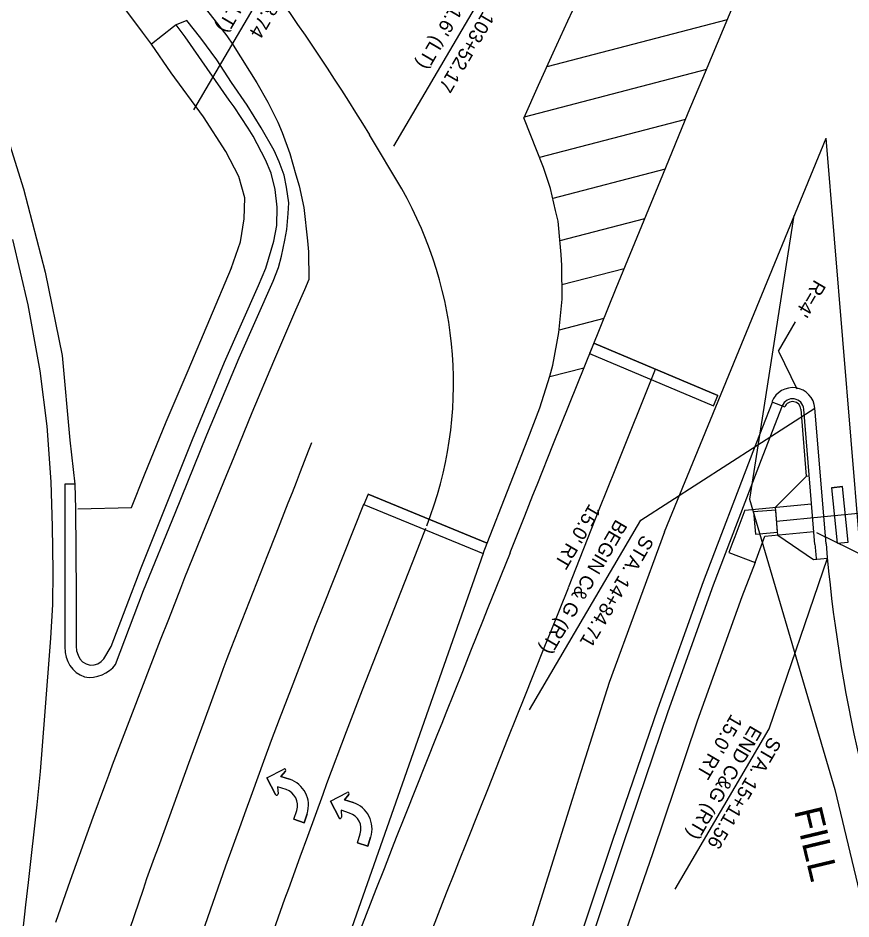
# Model space of a CAD drawing. Extents: x 1730210 to 1732101, y 650763 to 653427.
# Drawn here: x 1730371.6 to 1730520.8, y 652788.8 to 652950.2 of the extents above; entities that cross this region are included whole.
import ezdxf

# ---------------------------------------------------------------- set-up
doc = ezdxf.new("R2010")
doc.units = 0
for name, color, linetype in [('DESIGN - ROW - Slope Lines', 7, 'Continuous'), ('DESIGN - ROW - Slope Lines Text', 7, 'Continuous'), ('DESIGN - TRAFFIC CONTROL PERMANENT - Pavement Marking', 7, 'Continuous'), ('DESIGN - TRANSPORTATION - Curb Gutter and Sidewalk', 7, 'Continuous'), ('DESIGN - TRANSPORTATION - Edge of Traveled Way', 7, 'Continuous'), ('DESIGN - TRANSPORTATION - Shoulder Lines', 7, 'Continuous'), ('DESIGN - TRANSPORTATION - Text', 7, 'Continuous'), ('FUNCTIONAL - TRANSPORTATION - Preliminary Edge of Traveled Way', 7, 'Continuous'), ('SURVEY - TRANSPORTATION - Features', 7, 'Continuous')]:
    doc.layers.add(name, color=color, linetype=linetype)

msp = doc.modelspace()

# ---------------------------------------------------------------- linework, layer by layer
at = {"layer": 'DESIGN - ROW - Slope Lines'}
for p, q in [((1730510.54, 652914.84), (1730502.62, 652864.02)), ((1730502.62, 652864.02), (1730517.89, 652812.05)), ((1730517.89, 652812.05), (1730530.41, 652759.65))]:
    msp.add_line(p, q, dxfattribs=at)
at = {"layer": 'DESIGN - TRAFFIC CONTROL PERMANENT - Pavement Marking'}
for p, q in [((1730498.6, 652949.88), (1730466.28, 652941.47)), ((1730494.88, 652940.95), (1730462.22, 652932.45)), ((1730491.16, 652932.03), (1730465, 652925.22)), ((1730440.3, 652919.58), (1730434.56, 652929.27)), ((1730487.47, 652923.11), (1730467.37, 652917.88)), ((1730483.8, 652914.2), (1730468.65, 652910.26)), ((1730480.13, 652905.29), (1730469.01, 652902.39)), ((1730476.51, 652896.39), (1730468.51, 652894.3)), ((1730474.72, 652891.95), (1730496.91, 652882.58)), ((1730472.93, 652887.5), (1730466.81, 652885.91)), ((1730517.29, 652866.08), (1730519.28, 652866.29)), ((1730434.3, 652864.9), (1730455.63, 652856.17)), ((1730518.3, 652856.13), (1730520.29, 652856.34)), ((1730454.87, 652854.32), (1730406.19, 652715.68)), ((1730416.15, 652814.15), (1730419.16, 652815.69)), ((1730416.15, 652814.15), (1730419.16, 652815.69)), ((1730419.46, 652815.31), (1730418.66, 652814.38)), ((1730418.66, 652814.38), (1730419.46, 652815.31)), ((1730418.66, 652814.38), (1730420.2, 652813.88)), ((1730420.2, 652813.88), (1730418.66, 652814.38)), ((1730417.69, 652811.15), (1730416.15, 652814.15)), ((1730416.15, 652814.15), (1730417.69, 652811.15)), ((1730419.59, 652812.01), (1730418.05, 652812.5)), ((1730418.05, 652812.5), (1730418.15, 652811.28)), ((1730419.59, 652812.01), (1730418.05, 652812.5)), ((1730418.05, 652812.5), (1730418.15, 652811.28)), ((1730427.53, 652809.97), (1730430.54, 652811.5)), ((1730427.53, 652809.97), (1730430.54, 652811.5)), ((1730430.83, 652811.13), (1730430.04, 652810.19)), ((1730430.04, 652810.19), (1730430.83, 652811.13)), ((1730429.07, 652806.96), (1730427.53, 652809.97)), ((1730427.53, 652809.97), (1730429.07, 652806.96)), ((1730430.04, 652810.19), (1730431.58, 652809.69)), ((1730431.58, 652809.69), (1730430.04, 652810.19)), ((1730420.98, 652806.69), (1730421.49, 652808.29)), ((1730420.98, 652806.69), (1730421.49, 652808.29)), ((1730430.97, 652807.82), (1730429.43, 652808.32)), ((1730429.43, 652808.32), (1730429.53, 652807.09)), ((1730430.97, 652807.82), (1730429.43, 652808.32)), ((1730429.43, 652808.32), (1730429.53, 652807.09)), ((1730422.85, 652806.09), (1730420.98, 652806.69)), ((1730420.98, 652806.69), (1730422.85, 652806.09)), ((1730423.36, 652807.68), (1730422.85, 652806.09)), ((1730422.85, 652806.09), (1730423.36, 652807.68)), ((1730432.36, 652802.51), (1730432.87, 652804.1)), ((1730432.36, 652802.51), (1730432.87, 652804.1)), ((1730434.74, 652803.5), (1730434.23, 652801.9)), ((1730434.23, 652801.9), (1730434.74, 652803.5)), ((1730434.23, 652801.9), (1730432.36, 652802.51)), ((1730432.36, 652802.51), (1730434.23, 652801.9))]:
    msp.add_line(p, q, dxfattribs=at)
for points in [[(1730459.75, 652854.49), (1730462.34, 652861.01), (1730463.81, 652864.72), (1730464.55, 652866.58), (1730467.49, 652874.01), (1730478.69, 652901.8), (1730487.06, 652922.11), (1730491.64, 652933.19), (1730494.71, 652940.56), (1730500.09, 652953.46), (1730503.24, 652960.81), (1730505.59, 652966.32), (1730506.38, 652968.16), (1730507.95, 652971.83), (1730508.73, 652973.66), (1730510.3, 652977.33), (1730518.04, 652995.02)], [(1730385.19, 652976.62), (1730390.46, 652970.6), (1730397.86, 652961.16), (1730404.04, 652953.3), (1730407.74, 652948.58), (1730408.98, 652947.01), (1730410.08, 652945.35), (1730414.32, 652938.57), (1730416.33, 652935.1), (1730417.24, 652933.33), (1730418.1, 652931.52), (1730418.91, 652929.69), (1730420.24, 652925.92), (1730421.36, 652922.08), (1730421.91, 652920.16), (1730422.75, 652916.25), (1730423.43, 652910.3), (1730423.58, 652908.3), (1730423.67, 652903.38)], [(1730455.63, 652856.17), (1730462.91, 652874.77), (1730465.04, 652880.37), (1730466.86, 652886.08), (1730467.37, 652888.01), (1730468.1, 652891.93), (1730468.47, 652893.9), (1730469.03, 652899.86), (1730468.99, 652905.85), (1730468.89, 652907.84), (1730468.7, 652909.83), (1730468.3, 652913.8), (1730467.86, 652915.74), (1730466.97, 652919.64), (1730465.72, 652923.43), (1730462.16, 652932.31)], [(1730371.87, 652781.47), (1730372.99, 652791.4), (1730373.44, 652795.37), (1730375.01, 652809.27), (1730375.6, 652815.23), (1730376.39, 652825.2), (1730377.43, 652839.15), (1730377.82, 652845.14), (1730377.84, 652851.14), (1730377.77, 652859.14), (1730377.51, 652867.13), (1730376.77, 652877.11), (1730375.51, 652887.03), (1730373.37, 652898.83), (1730370.67, 652910.52)], [(1730423.67, 652903.38), (1730422.88, 652901.54), (1730421.29, 652897.88), (1730417.34, 652888.7), (1730413.44, 652879.51), (1730409.68, 652870.26), (1730408.92, 652868.41), (1730406.66, 652862.86), (1730405.16, 652859.17), (1730401.42, 652849.91), (1730400.69, 652848.05), (1730399.24, 652844.33), (1730398.51, 652842.47), (1730397.05, 652838.75), (1730392.01, 652825.72), (1730388.46, 652816.39), (1730387.75, 652814.52), (1730387.04, 652812.65), (1730384.99, 652807.03), (1730380.93, 652795.75), (1730379.6, 652791.98), (1730378.28, 652788.22)], [(1730470.16, 652848.2), (1730475.7, 652862.15), (1730478.64, 652869.55), (1730485.78, 652887.28)], [(1730390.82, 652784.73), (1730394.02, 652794.19), (1730394.66, 652796.08), (1730396.03, 652799.83), (1730396.71, 652801.71), (1730398.76, 652807.34), (1730402.18, 652816.72), (1730404.91, 652824.23), (1730406.28, 652827.98), (1730407.65, 652831.74), (1730408.33, 652833.61), (1730409.04, 652835.48), (1730409.77, 652837.34), (1730416.34, 652854.07), (1730417.8, 652857.79), (1730418.53, 652859.65), (1730419.26, 652861.51), (1730419.99, 652863.37), (1730420.71, 652865.23), (1730421.44, 652867.09), (1730422.17, 652868.95), (1730423.63, 652872.67), (1730424.23, 652874.19)], [(1730383.39, 652722.85), (1730386.34, 652732.15), (1730388.22, 652737.84), (1730395.16, 652758.69), (1730396.44, 652762.47), (1730397.08, 652764.36), (1730397.72, 652766.26), (1730400.29, 652773.82), (1730404.2, 652785.15), (1730408.8, 652798.35), (1730410.17, 652802.1), (1730411.54, 652805.86), (1730412.22, 652807.74), (1730413.58, 652811.49), (1730415.63, 652817.12), (1730417, 652820.88), (1730418.42, 652824.61), (1730420.57, 652830.2), (1730422.71, 652835.8), (1730423.43, 652837.66), (1730424.86, 652841.39), (1730426.33, 652845.1), (1730433.49, 652863.11)], [(1730394.34, 652719.4), (1730396.63, 652726.34), (1730398.51, 652732.03), (1730399.14, 652733.92), (1730400.42, 652737.7), (1730405.54, 652752.84), (1730412.73, 652773.6), (1730419.37, 652792.44), (1730420.06, 652794.32), (1730422.11, 652799.95), (1730423.48, 652803.7), (1730424.84, 652807.45), (1730426.21, 652811.21), (1730426.9, 652813.08), (1730430.4, 652822.43), (1730433.3, 652829.88), (1730442.75, 652854.07), (1730444.61, 652858.82)], [(1730406.19, 652715.68), (1730406.87, 652717.55), (1730408.25, 652721.3), (1730412.37, 652732.56), (1730414.44, 652738.18), (1730426.36, 652769.97), (1730435.72, 652794.2), (1730437.19, 652797.91), (1730438.66, 652801.63), (1730439.39, 652803.49), (1730440.86, 652807.2), (1730443.07, 652812.77), (1730444.55, 652816.48), (1730446.78, 652822.05), (1730447.52, 652823.9), (1730448.26, 652825.76), (1730451.23, 652833.18), (1730452.71, 652836.89), (1730454.94, 652842.45), (1730455.69, 652844.3), (1730459.76, 652854.48)], [(1730417.45, 652711.55), (1730418.14, 652713.43), (1730419.51, 652717.18), (1730423.63, 652728.42), (1730425.69, 652734), (1730437.58, 652765.71), (1730446.9, 652789.83), (1730448.35, 652793.51), (1730449.82, 652797.22), (1730450.55, 652799.08), (1730452.01, 652802.79), (1730454.22, 652808.33), (1730455.7, 652812.03), (1730459.4, 652821.3), (1730462.37, 652828.71), (1730463.85, 652832.42), (1730466.08, 652837.98), (1730466.83, 652839.84), (1730470.16, 652848.16)]]:
    msp.add_lwpolyline(points, dxfattribs=at)
for points in [[(1730474.72, 652891.95), (1730473.94, 652890.11), (1730496.14, 652880.74), (1730496.91, 652882.58)], [(1730517.29, 652866.08), (1730518.3, 652856.13), (1730520.29, 652856.34), (1730519.28, 652866.29)], [(1730434.3, 652864.9), (1730433.54, 652863.05), (1730454.87, 652854.32), (1730455.63, 652856.17)]]:
    msp.add_lwpolyline(points, close=True, dxfattribs=at)
for centre, radius, start, end in [((1732146.89, 652178.93), 1845.51, 143.31109, 155.90666), ((1730082.94, 652714.55), 412, 31.4096, 52.3723), ((1730379.58, 652884.74), 70, 338.653, 29.8433), ((1730419.27, 652815.47), 0.246, 319.6308, 117.079), ((1730419.27, 652815.47), 0.246, 319.6308, 117.079), ((1730418.68, 652809.2), 4.92, 342.079, 72.079), ((1730418.68, 652809.2), 4.92, 342.079, 72.079), ((1730417.91, 652811.26), 0.246, 207.079, 4.5722), ((1730417.91, 652811.26), 0.246, 207.079, 4.5722), ((1730418.68, 652809.2), 2.95, 342.079, 72.079), ((1730418.68, 652809.2), 2.95, 342.079, 72.079), ((1730430.65, 652811.29), 0.246, 319.6308, 117.079), ((1730430.65, 652811.29), 0.246, 319.6308, 117.079), ((1730430.06, 652805.01), 4.92, 342.079, 72.079), ((1730430.06, 652805.01), 4.92, 342.079, 72.079), ((1730429.28, 652807.07), 0.246, 207.079, 4.5722), ((1730429.28, 652807.07), 0.246, 207.079, 4.5722), ((1730430.06, 652805.01), 2.95, 342.079, 72.079), ((1730430.06, 652805.01), 2.95, 342.079, 72.079)]:
    msp.add_arc(centre, radius, start, end, dxfattribs=at)
at = {"layer": 'DESIGN - TRANSPORTATION - Curb Gutter and Sidewalk'}
for p, q in [((1730506.61, 652881.46), (1730508.94, 652880.55)), ((1730512.82, 652868.15), (1730511.83, 652880.12)), ((1730514.33, 652855.89), (1730512.33, 652880.16)), ((1730516.32, 652856.05), (1730514.32, 652880.33)), ((1730507.26, 652862.58), (1730512.82, 652868.15)), ((1730512.82, 652868.15), (1730513.32, 652868.19)), ((1730501.78, 652862.04), (1730513.73, 652863.21)), ((1730507.67, 652857.59), (1730507.26, 652862.58)), ((1730505.37, 652857.37), (1730514.14, 652858.23)), ((1730503.6, 652852.69), (1730505.37, 652857.37)), ((1730507.67, 652857.59), (1730514.06, 652853.2)), ((1730498.91, 652854.47), (1730503.6, 652852.69)), ((1730514.06, 652853.2), (1730516.55, 652853.43))]:
    msp.add_line(p, q, dxfattribs=at)
for centre, radius, start, end in [((1730510.33, 652880), 4, 4.7177, 158.5164), ((1730510.33, 652880), 2, 4.7177, 158.5164), ((1730510.33, 652880), 1.5, 4.7177, 158.5164), ((1732120.28, 652246.35), 1731.66, 159.17305, 159.44093), ((1730790.39, 652878.67), 277, 184.7177, 185.266)]:
    msp.add_arc(centre, radius, start, end, dxfattribs=at)
at = {"layer": 'DESIGN - TRANSPORTATION - Edge of Traveled Way'}
for p in [(1730487.38, 652858.16), (1730522.3, 652856.54)]:
    msp.add_line(p, (1730516.35, 652928.65), dxfattribs=at)
msp.add_lwpolyline([(1730487.38, 652858.16), (1730477.46, 652831.21), (1730472.03, 652814.07), (1730470.85, 652810.26), (1730463.69, 652787.38)], dxfattribs=at)
at = {"layer": 'DESIGN - TRANSPORTATION - Shoulder Lines'}
msp.add_arc((1730790.39, 652878.67), 275, 184.7177, 201.1154, dxfattribs=at)
at = {"layer": 'DESIGN - TRANSPORTATION - Text'}
for p, q in [((1730403.05, 652933.75), (1730423, 652967.74)), ((1730438.87, 652927.22), (1730458.82, 652961.22)), ((1730507.77, 652890.52), (1730510.86, 652895.78)), ((1730463.2, 652826.27), (1730483.15, 652860.26)), ((1730489.29, 652794.2), (1730506.13, 652822.89))]:
    msp.add_line(p, q, dxfattribs=at)
for points in [[(1730507.77, 652890.52), (1730511.06, 652883.76)], [(1730483.15, 652860.26), (1730514.32, 652880.33)], [(1730538.53, 652846.32), (1730514.68, 652858)], [(1730506.13, 652822.89), (1730516.55, 652853.43)]]:
    msp.add_lwpolyline(points, dxfattribs=at)
at = {"layer": 'FUNCTIONAL - TRANSPORTATION - Preliminary Edge of Traveled Way'}
msp.add_line((1730507.46, 652860.09), (1730560.92, 652865.34), dxfattribs=at)
msp.add_lwpolyline([(1730503.65, 652857.74), (1730507.64, 652858.09), (1730507.29, 652862.08), (1730503.3, 652861.73)], close=True, dxfattribs=at)
at = {"layer": 'SURVEY - TRANSPORTATION - Features'}
for points in [[(1730272.87, 653048.01), (1730283.61, 653041.79), (1730296.37, 653033.41), (1730308.39, 653023.98), (1730319.79, 653013.43), (1730330.32, 653002.12), (1730338.26, 652992.05), (1730340.57, 652988.7), (1730348.86, 652975.48), (1730356.23, 652962.2), (1730362.05, 652948.14), (1730367.97, 652934.08), (1730372.53, 652919.59), (1730376.43, 652904.68), (1730379.45, 652889.74), (1730380.84, 652874.59), (1730381.75, 652866.73)], [(1730395.47, 652945.52), (1730393.84, 652947.63), (1730383.29, 652961.88), (1730377.65, 652957.37)], [(1730386.94, 652835.44), (1730388.28, 652837.64), (1730393.65, 652851.71), (1730397.2, 652860.68), (1730402.85, 652874.72), (1730408.57, 652888.57), (1730414.62, 652902.27), (1730415.98, 652905.38), (1730417.42, 652910.21), (1730417.93, 652913.04), (1730418, 652916.31), (1730417.62, 652919.48), (1730416.9, 652922.4), (1730415.93, 652924.82), (1730413.71, 652929.02), (1730412.8, 652930.47), (1730410.27, 652934.29), (1730409.37, 652935.48), (1730401.5, 652946.83), (1730399.9, 652948.94)], [(1730389.02, 652834.42), (1730394.02, 652847.69), (1730399.74, 652861.53), (1730405.39, 652875.53), (1730411.2, 652889.34), (1730417.25, 652903.05), (1730418.23, 652905.5), (1730418.78, 652907.57), (1730419.36, 652910.4), (1730419.7, 652912.3), (1730419.97, 652915.17), (1730420.11, 652917.08), (1730419.69, 652919.87), (1730419.27, 652922.02), (1730418.37, 652924.44), (1730417.48, 652926.44), (1730415.13, 652930.55), (1730412.59, 652934.58), (1730409.79, 652938.64), (1730407.18, 652942.68), (1730404.32, 652946.57), (1730401.81, 652949.74), (1730399.9, 652948.94), (1730399.43, 652948.58), (1730395.47, 652945.52)], [(1730382.31, 652862.32), (1730391.91, 652862.53), (1730394.22, 652868.38), (1730398.09, 652877.87), (1730402.02, 652887.06), (1730405.92, 652896.25), (1730409.79, 652905.45), (1730409.77, 652905.34), (1730411.43, 652910.11), (1730412.09, 652914.21), (1730412.18, 652918.01), (1730411.14, 652921.82), (1730408.81, 652926.29), (1730404.79, 652932.52), (1730399.03, 652940.38), (1730395.47, 652945.52)], [(1730508.48, 652880.76), (1730505, 652871.87), (1730496.11, 652848.62), (1730487.95, 652825.93), (1730480, 652802.33), (1730472.07, 652778.64), (1730470.91, 652775.13), (1730466.22, 652760.83), (1730458.62, 652737.08), (1730450.72, 652710.55), (1730443.99, 652686.52), (1730443.09, 652683.31), (1730438.07, 652664.91), (1730437.67, 652663.46), (1730437.3, 652661.97), (1730437.15, 652661.4), (1730433.98, 652649.41), (1730430.87, 652637.21), (1730427.62, 652625.31), (1730423.53, 652610.75)], [(1730427.62, 652625.31), (1730425.73, 652625.88), (1730429.12, 652638.63), (1730432.09, 652649.99), (1730435.24, 652661.98), (1730435.39, 652662.56), (1730435.76, 652664.05), (1730436.16, 652665.49), (1730441.19, 652683.89), (1730442.07, 652687.1), (1730448.86, 652711.12), (1730456.77, 652737.65), (1730464.36, 652761.41), (1730469, 652775.72), (1730470.15, 652779.25), (1730478.09, 652802.93), (1730486.18, 652826.5), (1730494.38, 652849.31), (1730503.25, 652872.58), (1730506.72, 652881.42)], [(1730381.75, 652866.73), (1730379.93, 652866.69), (1730379.96, 652851.57), (1730379.95, 652837.67), (1730380.03, 652836.56)], [(1730381.75, 652866.73), (1730381.86, 652862.3), (1730381.99, 652847.08), (1730381.97, 652837.7), (1730382.07, 652836.87)], [(1730503.59, 652852.7), (1730501.24, 652846.56), (1730493.25, 652824.26), (1730485.31, 652800.68), (1730477.11, 652777.06), (1730475.91, 652773.56), (1730471.22, 652759.27), (1730463.62, 652735.54), (1730455.47, 652709.09), (1730448.75, 652685.07), (1730447.85, 652681.86)], [(1730380.03, 652836.56), (1730380.2, 652835.74), (1730380.47, 652834.95), (1730380.87, 652834.22), (1730381.41, 652833.58), (1730382.01, 652833), (1730382.7, 652832.54), (1730383.47, 652832.21), (1730384.29, 652832.08), (1730385.11, 652832.14), (1730385.88, 652832.33), (1730386.62, 652832.59), (1730387.3, 652832.93), (1730387.95, 652833.34), (1730388.54, 652833.83), (1730389.02, 652834.42)], [(1730382.07, 652836.87), (1730382.34, 652836.08), (1730382.67, 652835.44), (1730383.14, 652834.89), (1730383.77, 652834.51), (1730384.48, 652834.32), (1730385.2, 652834.35), (1730385.88, 652834.55), (1730386.46, 652834.94), (1730386.94, 652835.44)]]:
    msp.add_lwpolyline(points, dxfattribs=at)

# ---------------------------------------------------------------- texts
at = {"layer": 'DESIGN - ROW - Slope Lines Text'}
msp.add_text('FILL', height=5, rotation=283.4376, dxfattribs=at).set_placement((1730510.57, 652808.26))
at = {"layer": 'DESIGN - TRANSPORTATION - Text'}
for s, p in [("OFF. 40.6' (LT)", (1730418.54, 652968.04)), ('STA. 6+68.74', (1730423.28, 652965.26)), ("OFF. 41.6' (LT)", (1730454.36, 652961.52)), ('STA. 103+52.17', (1730459.1, 652958.73)), ("R=4'", (1730514.26, 652903.48)), ("15.0' RT", (1730473.95, 652863.35)), ('BEGIN C& G (RT)', (1730478.69, 652860.56)), ('STA. 14+84.71', (1730483.43, 652857.78)), ("15.0' RT", (1730499.37, 652825.7)), ('END C&G (RT)', (1730502.82, 652823.68)), ('STA. 15+11.56', (1730506.27, 652821.65))]:
    msp.add_text(s, height=2.5, rotation=239.5926, dxfattribs=at).set_placement(p)

doc.saveas('drawing.dxf')
